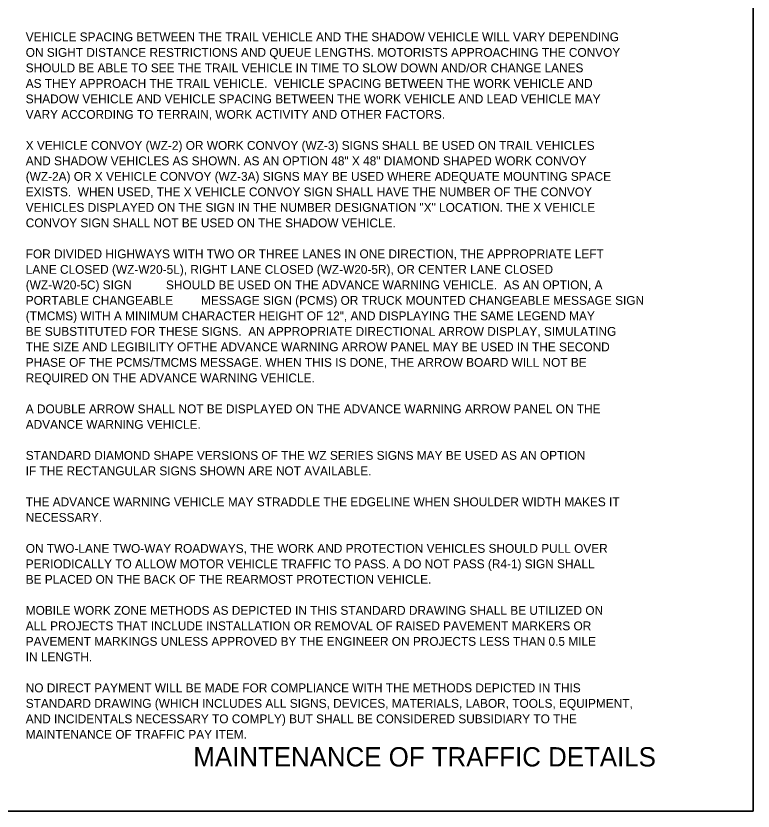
# Model space of a CAD drawing. Extents: x 1416408 to 1429341, y 372694 to 383211.
# Drawn here: x 1428159 to 1428995, y 372694 to 373596 of the extents above; entities that cross this region are included whole.
import ezdxf

# ---------------------------------------------------------------- set-up
doc = ezdxf.new("R2010")
doc.units = 0
for name, color, linetype in [('Default', 7, 'Continuous'), ('DSN_DRFT_Junk-No-Plot', 7, 'Continuous'), ('R_Border Notes', 7, 'Continuous'), ('Working Level 1', 7, 'Continuous')]:
    doc.layers.add(name, color=color, linetype=linetype)

msp = doc.modelspace()

# ---------------------------------------------------------------- linework, layer by layer
at = {"layer": 'Default'}
for points in [[(1426234.86, 374479.9), (1426234.86, 372693.86), (1428995.11, 372693.86), (1428995.11, 374479.9)], [(1426234.86, 374479.9), (1426234.86, 372693.86), (1428995.11, 372693.86), (1428995.11, 374479.9)], [(1426234.86, 374479.9), (1428995.11, 374479.9), (1428995.11, 372693.86), (1426234.86, 372693.86)], [(1426234.86, 374479.9), (1426234.86, 372693.86), (1428995.11, 372693.86), (1428995.11, 374479.9)]]:
    msp.add_lwpolyline(points, close=True, dxfattribs=at)
at = {"layer": 'DSN_DRFT_Junk-No-Plot'}
msp.add_lwpolyline([(1426234.86, 374479.9), (1428995.11, 374479.9), (1428995.11, 372693.86), (1426234.86, 372693.86)], close=True, dxfattribs=at)

# ---------------------------------------------------------------- texts
at = {"layer": 'R_Border Notes'}
msp.add_text('MAINTENANCE OF TRAFFIC DETAILS', height=21.9196, dxfattribs=at).set_placement((1428360.47, 372744.47))
at = {"layer": 'Working Level 1'}
for s, height, p in [('VEHICLE SPACING BETWEEN THE TRAIL VEHICLE AND THE SHADOW VEHICLE WILL VARY DEPENDING ', 10.0465, (1428170.44, 373567.03)), ('ON SIGHT DISTANCE RESTRICTIONS AND QUEUE LENGTHS. MOTORISTS APPROACHING THE CONVOY ', 10.0465, (1428170.44, 373549.45)), ('SHOULD BE ABLE TO SEE THE TRAIL VEHICLE IN TIME TO SLOW DOWN AND/OR CHANGE LANES ', 10.0465, (1428170.44, 373531.86)), ('AS THEY APPROACH THE TRAIL VEHICLE.  VEHICLE SPACING BETWEEN THE WORK VEHICLE AND ', 10.0465, (1428170.44, 373514.28)), ('SHADOW VEHICLE AND VEHICLE SPACING BETWEEN THE WORK VEHICLE AND LEAD VEHICLE MAY ', 10.0465, (1428170.44, 373496.7)), ('VARY ACCORDING TO TERRAIN, WORK ACTIVITY AND OTHER FACTORS.', 10.0465, (1428170.44, 373479.12)), ('X VEHICLE CONVOY (WZ-2) OR WORK CONVOY (WZ-3) SIGNS SHALL BE USED ON TRAIL VEHICLES', 10.0465, (1428170.44, 373443.96)), ('AND SHADOW VEHICLES AS SHOWN. AS AN OPTION 48" X 48" DIAMOND SHAPED WORK CONVOY', 10.0465, (1428170.44, 373426.38)), ('(WZ-2A) OR X VEHICLE CONVOY (WZ-3A) SIGNS MAY BE USED WHERE ADEQUATE MOUNTING SPACE', 10.0465, (1428170.44, 373408.8)), ('EXISTS.  WHEN USED, THE X VEHICLE CONVOY SIGN SHALL HAVE THE NUMBER OF THE CONVOY', 10.0465, (1428170.44, 373391.21)), ('VEHICLES DISPLAYED ON THE SIGN IN THE NUMBER DESIGNATION "X" LOCATION. THE X VEHICLE', 10.0465, (1428170.44, 373373.63)), ('CONVOY SIGN SHALL NOT BE USED ON THE SHADOW VEHICLE.', 10.0465, (1428170.44, 373356.05)), ('FOR DIVIDED HIGHWAYS WITH TWO OR THREE LANES IN ONE DIRECTION, THE APPROPRIATE LEFT ', 10.0465, (1428170.44, 373320.89)), ('LANE CLOSED (WZ-W20-5L), RIGHT LANE CLOSED (WZ-W20-5R), OR CENTER LANE CLOSED ', 10.0465, (1428170.44, 373303.31)), ('(WZ-W20-5C) SIGN', 10.0465, (1428170.44, 373285.73)), ('SHOULD BE USED ON THE ADVANCE WARNING VEHICLE.  AS AN OPTION, A ', 10.0465, (1428329.43, 373285.73)), ('PORTABLE CHANGEABLE', 10.0465, (1428170.44, 373268.14)), ('MESSAGE SIGN (PCMS) OR TRUCK MOUNTED CHANGEABLE MESSAGE SIGN ', 10.0465, (1428369.17, 373268.14)), ('(TMCMS) WITH A MINIMUM CHARACTER HEIGHT OF 12", AND DISPLAYING THE SAME LEGEND MAY ', 10.0465, (1428170.44, 373250.56)), ('BE SUBSTITUTED FOR THESE SIGNS.  AN APPROPRIATE DIRECTIONAL ARROW DISPLAY, SIMULATING ', 10.0465, (1428170.44, 373232.98)), ('THE SIZE AND LEGIBILITY OFTHE ADVANCE WARNING ARROW PANEL MAY BE USED IN THE SECOND ', 10.0465, (1428170.44, 373215.4)), ('PHASE OF THE PCMS/TMCMS MESSAGE. WHEN THIS IS DONE, THE ARROW BOARD WILL NOT BE ', 10.0465, (1428170.44, 373197.82)), ('REQUIRED ON THE ADVANCE WARNING VEHICLE.', 10.0465, (1428170.44, 373180.24)), ('A DOUBLE ARROW SHALL NOT BE DISPLAYED ON THE ADVANCE WARNING ARROW PANEL ON THE ', 10.0465, (1428170.44, 373145.08)), ('ADVANCE WARNING VEHICLE. ', 10.0465, (1428170.44, 373127.49)), ('STANDARD DIAMOND SHAPE VERSIONS OF THE WZ SERIES SIGNS MAY BE USED AS AN OPTION ', 10.0465, (1428170.44, 373092.33)), ('IF THE RECTANGULAR SIGNS SHOWN ARE NOT AVAILABLE.', 10.0465, (1428170.44, 373074.75)), ('THE ADVANCE WARNING VEHICLE MAY STRADDLE THE EDGELINE WHEN SHOULDER WIDTH MAKES IT ', 10.0465, (1428170.44, 373039.59)), ('NECESSARY.', 10.046, (1428170.44, 373022.01)), ('ON TWO-LANE TWO-WAY ROADWAYS, THE WORK AND PROTECTION VEHICLES SHOULD PULL OVER', 10.0465, (1428170.44, 372986.84)), ('PERIODICALLY TO ALLOW MOTOR VEHICLE TRAFFIC TO PASS. A DO NOT PASS (R4-1) SIGN SHALL ', 10.0465, (1428170.44, 372969.26)), ('BE PLACED ON THE BACK OF THE REARMOST PROTECTION VEHICLE.', 10.0465, (1428170.44, 372951.68)), ('MOBILE WORK ZONE METHODS AS DEPICTED IN THIS STANDARD DRAWING SHALL BE UTILIZED ON ', 10.0465, (1428170.44, 372916.52)), ('ALL PROJECTS THAT INCLUDE INSTALLATION OR REMOVAL OF RAISED PAVEMENT MARKERS OR ', 10.0465, (1428170.44, 372898.94)), ('PAVEMENT MARKINGS UNLESS APPROVED BY THE ENGINEER ON PROJECTS LESS THAN 0.5 MILE ', 10.0465, (1428170.44, 372881.36)), ('IN LENGTH.', 10.046, (1428170.44, 372863.77)), ('NO DIRECT PAYMENT WILL BE MADE FOR COMPLIANCE WITH THE METHODS DEPICTED IN THIS ', 10.0465, (1428170.44, 372828.61)), ('STANDARD DRAWING (WHICH INCLUDES ALL SIGNS, DEVICES, MATERIALS, LABOR, TOOLS, EQUIPMENT, ', 10.0465, (1428170.44, 372811.03)), ('AND INCIDENTALS NECESSARY TO COMPLY) BUT SHALL BE CONSIDERED SUBSIDIARY TO THE ', 10.0465, (1428170.44, 372793.45)), ('MAINTENANCE OF TRAFFIC PAY ITEM.', 10.0465, (1428170.44, 372775.87))]:
    msp.add_text(s, height=height, dxfattribs=at).set_placement(p)

doc.saveas('drawing.dxf')
